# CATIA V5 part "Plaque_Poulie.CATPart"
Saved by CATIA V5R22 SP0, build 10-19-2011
Part number: Plaque_Poulie
Bounding box of the stored display mesh (mm): x -20 to 20, y -33.5 to 33.5, z 0 to 3
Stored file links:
  U:\S9A\PER\CAO\Assemblage\Cadre\Chariot_X\Plaque_Poulie.CATPart
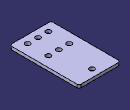
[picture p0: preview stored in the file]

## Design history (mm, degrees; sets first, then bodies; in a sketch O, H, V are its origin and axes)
Body1 (main body)
  Sketch1 on xy-plane, origin (0, 0, 0), H (1, 0, 0), V (0, 1, 0)
    line L1 (20, 33.5) -> (20, -33.5)
    line L2 (20, -33.5) -> (-20, -33.5)
    line L3 (-20, -33.5) -> (-20, 33.5)
    line L4 (-20, 33.5) -> (20, 33.5)
    length L1 = 67
    length L4 = 40
    vertical: L1 V, L3 V
    horizontal: L2 H, L4 H
    equidistance: L1 L3 O, L2 L4 O
  Pad1: profile Sketch1, direction (0, 0, 1), length 3
  Sketch2 on end face of Pad1, origin (-2.606, -38.1401, 3), H (1, 0, 0), V (0, 1, 0)
    point P1 (-7.394, 12.1401)
    reference projected line E1 (-17.394, 71.6401) -> (-17.394, 4.6401) from edge [face of Pad1 from Sketch1.L3 | end face of Pad1]
    reference projected line E2 (-17.394, 4.6401) -> (22.606, 4.6401) from edge [face of Pad1 from Sketch1.L2 | end face of Pad1]
    distance P1 E1 = 10
    distance P1 E2 = 7.5
  Hole1: placed by Sketch2, at (-10, -26, 3) direction (0, 0, -1), diameter 5, through (limit type 3)
  RectPattern1: of Hole1, direction 1 instances 3, spacing 10, along end face of Pad1, direction 2 instances 2, spacing 20, along end face of Pad1
  Fillet1: radius 2, on edge [face of Pad1 from Sketch1.L2 | face of Pad1 from Sketch1.L3]; edge [face of Pad1 from Sketch1.L1 | face of Pad1 from Sketch1.L2]; edge [face of Pad1 from Sketch1.L3 | face of Pad1 from Sketch1.L4]; edge [face of Pad1 from Sketch1.L4 | face of Pad1 from Sketch1.L1]
  Sketch3 on end face of Pad1, origin (-6.1214, 16.614, 3), H (1, 0, 0), V (0, 1, 0)
    point P1 (6.1214, 9.386)
    reference projected line E1 (26.1214, 16.886) -> (-13.8786, 16.886) from edge [face of Pad1 from Sketch1.L4 | end face of Pad1]
    reference projected line E2 (26.1214, -50.114) -> (26.1214, 16.886) from edge [face of Pad1 from Sketch1.L1 | end face of Pad1]
    distance P1 E1 = 7.5
    distance P1 E2 = 20
  Hole2: placed by Sketch3, at (0, 26, 3) direction (0, 0, -1), diameter 5, through (limit type 3)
